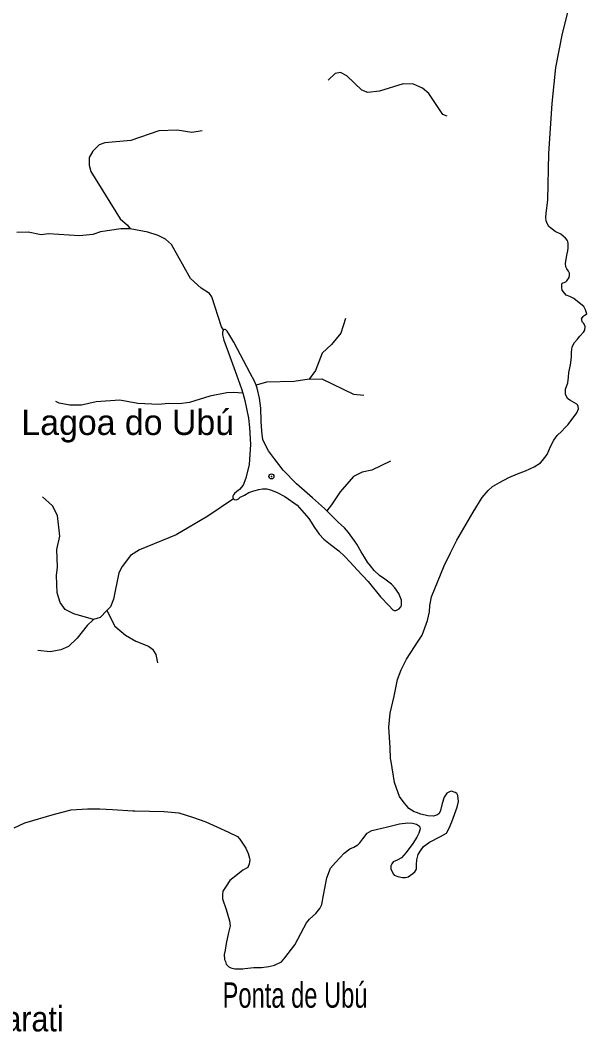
# Model space of a CAD drawing. Extents: x 317.8 to 344.1, y 7676.8 to 7704.8.
# Drawn here: x 334.107 to 335.897, y 7698.262 to 7701.462 of the extents above; entities that cross this region are included whole.
import ezdxf
from ezdxf.enums import TextEntityAlignment as Align

# ---------------------------------------------------------------- set-up
doc = ezdxf.new("R2010")
doc.units = 0
doc.header["$LTSCALE"] = 0.032
doc.header["$PDMODE"] = 32
doc.header["$PDSIZE"] = 0.016
doc.layers.add('2', color=7, linetype='Continuous', lineweight=25)
doc.layers.add('7', color=7, linetype='Continuous', lineweight=25)
doc.layers.add('54', color=7, linetype='Continuous')
doc.layers.add('61', color=7, linetype='Continuous')

msp = doc.modelspace()

# ---------------------------------------------------------------- linework, layer by layer
at = {"layer": '2'}
for points in [[(335.8276, 7700.5972), (335.82, 7700.608), (335.8181, 7700.616), (335.8181, 7700.6209), (335.8181, 7700.6251), (335.8187, 7700.6282), (335.8212, 7700.6306), (335.8255, 7700.6319), (335.8316, 7700.6337), (335.8346, 7700.6374), (335.8414, 7700.6478), (335.8432, 7700.6557), (335.8426, 7700.6612), (335.8395, 7700.6679), (335.8346, 7700.6753), (335.831, 7700.682), (335.8304, 7700.6924), (335.834, 7700.7181), (335.8371, 7700.7328), (335.8389, 7700.7419), (335.8389, 7700.7487), (335.8389, 7700.7554), (335.8377, 7700.7615), (335.8353, 7700.7658), (335.8304, 7700.7719), (335.8151, 7700.7847), (335.7973, 7700.7939), (335.7827, 7700.8049), (335.7772, 7700.8098), (335.7729, 7700.8165), (335.7686, 7700.8269), (335.768, 7700.8379), (335.7692, 7700.8514), (335.7741, 7700.893), (335.7773, 7701.04), (335.7879, 7701.1987), (335.7993, 7701.3125), (335.8205, 7701.4201), (335.85, 7701.5379)], [(335.8972, 7700.5328), (335.8935, 7700.5452), (335.8876, 7700.556), (335.8733, 7700.5674), (335.856, 7700.5812), (335.8437, 7700.5876), (335.8323, 7700.5925), (335.8276, 7700.5972)], [(335.4065, 7699.6372), (335.4468, 7699.7353), (335.4664, 7699.7766), (335.4861, 7699.8169), (335.5377, 7699.9058), (335.5666, 7699.9522), (335.5852, 7699.9739), (335.5997, 7699.9863), (335.6214, 7699.9998), (335.6513, 7700.0153), (335.6782, 7700.0266), (335.704, 7700.0359), (335.7309, 7700.0494), (335.7505, 7700.0618), (335.7577, 7700.069), (335.7722, 7700.0876), (335.7825, 7700.1134), (335.7929, 7700.133), (335.8032, 7700.1485), (335.8187, 7700.162), (335.828, 7700.1723), (335.8383, 7700.1826), (335.8662, 7700.2198), (335.8714, 7700.2322), (335.8704, 7700.2394), (335.8683, 7700.2456), (335.8662, 7700.2477), (335.859, 7700.2518), (335.8435, 7700.2601), (335.8363, 7700.2653), (335.8342, 7700.2704), (335.8301, 7700.2777), (335.8301, 7700.2942), (335.8373, 7700.3148), (335.8394, 7700.3324), (335.8404, 7700.3469), (335.8456, 7700.3717), (335.8487, 7700.3954), (335.8487, 7700.412), (335.8507, 7700.4285), (335.858, 7700.4419), (335.8683, 7700.4533), (335.8755, 7700.4626), (335.8869, 7700.475), (335.891, 7700.4812), (335.892, 7700.4925), (335.8879, 7700.5029), (335.8827, 7700.508), (335.8812, 7700.515), (335.8807, 7700.5173), (335.8858, 7700.5246), (335.8889, 7700.5277), (335.8972, 7700.5328)], [(334.7489, 7700.4827), (334.7475, 7700.4806), (334.746, 7700.4748), (334.746, 7700.4669), (334.7504, 7700.4497), (334.7648, 7700.4098)], [(334.8518, 7700.307), (334.8473, 7700.3196), (334.8337, 7700.3455), (334.782, 7700.4432), (334.7662, 7700.4698), (334.7604, 7700.4784), (334.7561, 7700.482), (334.7539, 7700.4834), (334.7518, 7700.4834), (334.7489, 7700.4827)], [(334.7648, 7700.4098), (334.7905, 7700.3395), (334.8064, 7700.2952), (334.8099, 7700.2825)], [(335.0755, 7699.9097), (335.0686, 7699.9166), (335.0305, 7699.9504), (334.9795, 7699.9956), (334.9378, 7700.038), (334.9105, 7700.074), (334.8912, 7700.0991), (334.8797, 7700.1221), (334.8739, 7700.1357), (334.8718, 7700.1515), (334.8696, 7700.176), (334.8682, 7700.1939), (334.8674, 7700.2349), (334.8631, 7700.2658), (334.8552, 7700.2974), (334.8518, 7700.307)], [(334.8099, 7700.2825), (334.8164, 7700.2586), (334.8279, 7700.2033), (334.8308, 7700.1731), (334.8344, 7700.1199), (334.8301, 7700.056), (334.8193, 7700.0136), (334.8114, 7699.9906), (334.7992, 7699.9777), (334.7913, 7699.9705), (334.7841, 7699.9648), (334.7805, 7699.9604), (334.7784, 7699.9561), (334.7784, 7699.9525), (334.7791, 7699.9482), (334.7804, 7699.9473)], [(334.7804, 7699.9473), (334.7834, 7699.9454), (334.7906, 7699.9446), (334.7963, 7699.9475), (334.8021, 7699.9525), (334.815, 7699.9597), (334.8287, 7699.9676), (334.8445, 7699.9734), (334.861, 7699.9777), (334.8725, 7699.9791), (334.8861, 7699.9791), (334.9012, 7699.9755), (334.9185, 7699.9676), (334.9429, 7699.9554), (334.9824, 7699.9274), (335.0183, 7699.885), (335.037, 7699.857), (335.0513, 7699.8354), (335.0657, 7699.8204), (335.0873, 7699.8031), (335.1131, 7699.783), (335.1318, 7699.7665), (335.149, 7699.7471), (335.1713, 7699.7227), (335.2065, 7699.686), (335.2453, 7699.6379), (335.2712, 7699.6099), (335.2848, 7699.5969), (335.2884, 7699.5948), (335.2942, 7699.5948), (335.3006, 7699.5977), (335.3042, 7699.5998), (335.3092, 7699.6056), (335.3114, 7699.6106), (335.3121, 7699.6192), (335.3114, 7699.6271), (335.3028, 7699.648), (335.2906, 7699.6666), (335.2798, 7699.6774), (335.259, 7699.6932), (335.2424, 7699.7054), (335.2252, 7699.7212), (335.2137, 7699.7356), (335.2044, 7699.7478), (335.195, 7699.7636), (335.1842, 7699.7801), (335.1706, 7699.8038), (335.1627, 7699.8146), (335.144, 7699.8412), (335.1311, 7699.8556), (335.111, 7699.8742), (335.1024, 7699.8829), (335.0755, 7699.9097)], [(335.3642, 7699.4972), (335.3766, 7699.5163), (335.3941, 7699.5628), (335.4003, 7699.5907), (335.4013, 7699.6103), (335.4065, 7699.6372)], [(334.9106, 7698.4719), (334.9323, 7698.4832), (334.9427, 7698.4956), (334.9747, 7698.537), (335.0026, 7698.5907), (335.0119, 7698.6062), (335.0212, 7698.6175), (335.0408, 7698.6361), (335.0532, 7698.6516), (335.0594, 7698.664), (335.0656, 7698.694), (335.0759, 7698.7487), (335.0873, 7698.7797), (335.1028, 7698.7973), (335.1307, 7698.8262), (335.1482, 7698.8407), (335.1606, 7698.8458), (335.1741, 7698.8531), (335.1803, 7698.8593), (335.1896, 7698.8717), (335.203, 7698.8903), (335.2175, 7698.8985), (335.2319, 7698.9016), (335.267, 7698.9099), (335.3053, 7698.9192), (335.3321, 7698.9223), (335.3466, 7698.9213), (335.359, 7698.9182), (335.3683, 7698.912), (335.3704, 7698.9037), (335.3662, 7698.8903), (335.36, 7698.8768), (335.3476, 7698.8572), (335.3259, 7698.8293), (335.3115, 7698.8118), (335.298, 7698.8045), (335.2856, 7698.7994), (335.2815, 7698.7932), (335.2784, 7698.787), (335.2784, 7698.7766), (335.2867, 7698.7601), (335.2887, 7698.757), (335.3001, 7698.7529), (335.3146, 7698.7498), (335.3239, 7698.7498), (335.3332, 7698.7518), (335.3404, 7698.757), (335.3476, 7698.7622), (335.3538, 7698.7673), (335.359, 7698.7756), (335.359, 7698.7911), (335.36, 7698.8056), (335.3642, 7698.8221), (335.3714, 7698.8345), (335.3817, 7698.8479), (335.4003, 7698.8613), (335.4354, 7698.8799), (335.454, 7698.8903), (335.4623, 7698.9058), (335.4706, 7698.9254), (335.4871, 7698.9719), (335.4923, 7698.9905), (335.4902, 7699.0091), (335.4861, 7699.0153), (335.4809, 7699.0184), (335.4695, 7699.0225), (335.4633, 7699.0204), (335.4551, 7699.0163), (335.4468, 7699.0039), (335.4406, 7698.9843), (335.4354, 7698.9615), (335.4303, 7698.9523), (335.4251, 7698.9481), (335.4127, 7698.944), (335.3951, 7698.945), (335.3724, 7698.9502), (335.359, 7698.9554), (335.3518, 7698.9574), (335.3352, 7698.9677), (335.327, 7698.977), (335.3197, 7698.9863), (335.3053, 7699.006), (335.296, 7699.0328), (335.2898, 7699.0504), (335.2789, 7699.1168), (335.2774, 7699.1258), (335.2763, 7699.1609), (335.2712, 7699.225), (335.2763, 7699.2694), (335.2887, 7699.3231), (335.2909, 7699.3343), (335.2991, 7699.3758), (335.3104, 7699.4068), (335.328, 7699.4409), (335.3642, 7699.4972)], [(334.0873, 7698.9068), (334.1214, 7698.9223), (334.2154, 7698.9502), (334.2681, 7698.9636), (334.3187, 7698.9667), (334.358, 7698.9667), (334.3983, 7698.9646), (334.4623, 7698.9605), (334.4693, 7698.9604), (334.5615, 7698.9585), (334.608, 7698.9543), (334.6513, 7698.9409), (334.6937, 7698.9254), (334.7278, 7698.9099), (334.765, 7698.8934), (334.7929, 7698.8799), (334.8011, 7698.8706), (334.8197, 7698.8427), (334.827, 7698.8252), (334.8311, 7698.8107), (334.8321, 7698.8045), (334.8301, 7698.7932), (334.8259, 7698.7818), (334.8104, 7698.7725), (334.7929, 7698.7591), (334.7691, 7698.7405), (334.7578, 7698.7219), (334.7474, 7698.7064), (334.7454, 7698.6961), (334.7464, 7698.6826), (334.7578, 7698.6485), (334.7681, 7698.6124), (334.7701, 7698.5969), (334.765, 7698.5762), (334.7578, 7698.5411), (334.754, 7698.5197), (334.7516, 7698.506), (334.7526, 7698.4905), (334.7557, 7698.4843), (334.7578, 7698.476), (334.766, 7698.4667), (334.7722, 7698.4636), (334.7846, 7698.4605), (334.797, 7698.4605), (334.8098, 7698.4612)], [(334.8098, 7698.4612), (334.8166, 7698.4616), (334.8445, 7698.4647), (334.8693, 7698.4647), (334.892, 7698.4678), (334.9106, 7698.4719)]]:
    msp.add_lwpolyline(points, dxfattribs=at)
msp.add_point((334.9006, 7700.0188), dxfattribs=at)
at = {"layer": '7'}
for points in [[(335.4561, 7701.1586), (335.4424, 7701.1641), (335.3979, 7701.2296), (335.378, 7701.2469), (335.35, 7701.2601), (335.3171, 7701.2604), (335.2422, 7701.2373), (335.2057, 7701.2335), (335.1866, 7701.2405), (335.1388, 7701.2858), (335.1191, 7701.297), (335.1016, 7701.2937), (335.0796, 7701.2727)], [(334.6819, 7701.1121), (334.6486, 7701.1065), (334.6027, 7701.1136), (334.5451, 7701.1119), (334.456, 7701.081), (334.3745, 7701.0745), (334.3558, 7701.0674), (334.336, 7701.0481), (334.3246, 7701.0278), (334.324, 7701.0028), (334.3296, 7700.9832), (334.4224, 7700.8336), (334.446, 7700.813), (334.4543, 7700.8018)], [(334.4543, 7700.8018), (334.4243, 7700.8022), (334.3602, 7700.7926), (334.3358, 7700.7841), (334.2942, 7700.7795), (334.1956, 7700.786), (334.1728, 7700.7828), (334.1316, 7700.7909), (334.0962, 7700.7904)], [(334.7489, 7700.4827), (334.7432, 7700.4923), (334.7127, 7700.5872), (334.7046, 7700.5977), (334.6787, 7700.6143), (334.6444, 7700.6443), (334.5846, 7700.752), (334.5655, 7700.7695), (334.5428, 7700.781), (334.5098, 7700.7917), (334.4543, 7700.8018)], [(335.1342, 7700.518), (335.1199, 7700.4713), (335.0906, 7700.4361), (335.0609, 7700.4089), (335.0403, 7700.3539), (335.02, 7700.3258)], [(335.02, 7700.3258), (334.9723, 7700.3191), (334.8848, 7700.3165), (334.8518, 7700.307)], [(335.02, 7700.3258), (335.0598, 7700.3277), (335.1596, 7700.279), (335.1921, 7700.2759)], [(334.8099, 7700.2825), (334.7804, 7700.2839), (334.7601, 7700.283), (334.7058, 7700.2722), (334.6411, 7700.2529), (334.6086, 7700.2482), (334.5743, 7700.2497), (334.5448, 7700.2457), (334.4785, 7700.249), (334.4218, 7700.2595), (334.3469, 7700.2546), (334.3005, 7700.2441), (334.2634, 7700.2441), (334.2301, 7700.2504), (334.2189, 7700.2555)], [(335.2768, 7700.0673), (335.2183, 7700.0385), (335.1877, 7700.0323), (335.1603, 7700.0183), (335.1176, 7699.97), (335.0908, 7699.9287), (335.0755, 7699.9097)], [(334.3384, 7699.5657), (334.276, 7699.5834), (334.2488, 7699.598), (334.2325, 7699.6197), (334.223, 7699.6501), (334.2212, 7699.705), (334.2246, 7699.7317), (334.2222, 7699.787), (334.2319, 7699.83), (334.2245, 7699.895), (334.2083, 7699.9252), (334.1765, 7699.954)], [(334.7804, 7699.9473), (334.6995, 7699.8929), (334.5998, 7699.8342), (334.4838, 7699.7868), (334.4556, 7699.7684), (334.4288, 7699.7336), (334.4184, 7699.7132), (334.401, 7699.6302), (334.3923, 7699.6061), (334.3805, 7699.594)], [(334.3805, 7699.594), (334.3595, 7699.5724), (334.3384, 7699.5657)], [(334.3805, 7699.594), (334.406, 7699.545), (334.4391, 7699.5163), (334.4722, 7699.4974), (334.5118, 7699.4817), (334.5246, 7699.472), (334.5356, 7699.455), (334.5409, 7699.4291)], [(334.3384, 7699.5657), (334.3177, 7699.5467), (334.2863, 7699.507), (334.259, 7699.4807), (334.2354, 7699.47), (334.2007, 7699.4639), (334.1619, 7699.4674)]]:
    msp.add_lwpolyline(points, dxfattribs=at)

# ---------------------------------------------------------------- texts
at = {"layer": '54', "width": 0.9}
msp.add_text('Ilha de Parati', height=0.08, dxfattribs=at).set_placement((333.6764, 7698.2628))
at = {"layer": '61'}
msp.add_text('Lagoa do Ubú', height=0.08, dxfattribs=at).set_placement((334.7824, 7700.1497), align=Align.RIGHT)
at = {"layer": '61', "width": 0.7}
msp.add_text('Ponta de Ubú', height=0.08, dxfattribs=at).set_placement((334.7462, 7698.3378))

doc.saveas('drawing.dxf')
